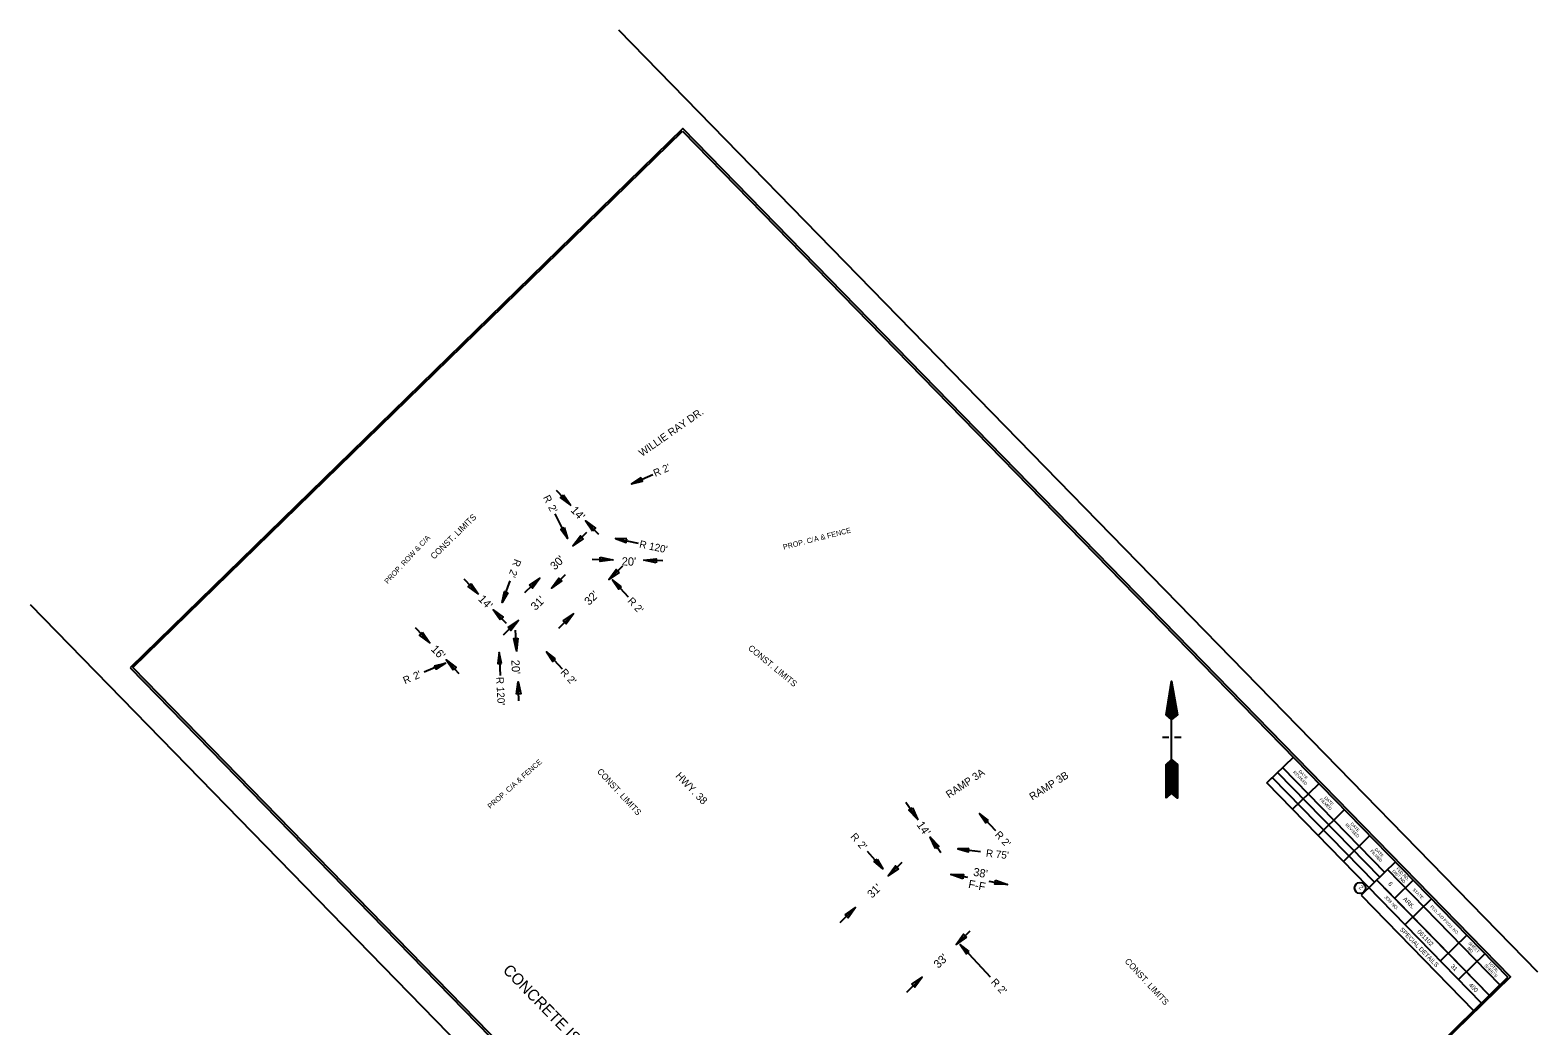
# Model space of a CAD drawing. Extents: x 1309825 to 1312816, y 238906 to 242017.
# Drawn here: x 1309825 to 1310833, y 241351 to 242017 of the extents above; entities that cross this region are included whole.
import ezdxf

# ---------------------------------------------------------------- set-up
doc = ezdxf.new("R2010")
doc.units = 0
for name, color, linetype in [('R_Annotation', 7, 'Continuous'), ('R_Border', 7, 'Continuous'), ('R_Dimension', 7, 'Continuous'), ('R_No Plot', 7, 'Continuous'), ('R_North Arrow', 7, 'Continuous')]:
    doc.layers.add(name, color=color, linetype=linetype)

msp = doc.modelspace()

# ---------------------------------------------------------------- linework, layer by layer
at = {"layer": 'R_Border'}
for p, q in [((1310832.9, 241386.9), (1310218.4, 242016.8)), ((1309893.3, 241590.7), (1310261, 241949.3)), ((1310261, 241949.3), (1310812.9, 241383.5)), ((1309824.7, 241632.8), (1310439.2, 241002.8)), ((1310445.2, 241024.8), (1309893.3, 241590.7)), ((1310651.6, 241513.5), (1310669.4, 241530.7)), ((1310651.6, 241513.5), (1310655.3, 241517.1)), ((1310655.3, 241517.1), (1310723.7, 241447)), ((1310658.8, 241520.5), (1310727.1, 241450.4)), ((1310662.1, 241523.7), (1310730.5, 241453.6)), ((1310795.2, 241366.2), (1310651.6, 241513.5)), ((1310668.8, 241495.8), (1310686.2, 241512.7)), ((1310685.9, 241478.3), (1310703.2, 241495.3)), ((1310702.8, 241461), (1310720.1, 241477.9)), ((1310737.6, 241460.7), (1310714.8, 241438.3)), ((1310807.6, 241378.3), (1310732.4, 241455.5)), ((1310800.5, 241371.4), (1310725.3, 241448.5)), ((1310749.6, 241448.4), (1310737.2, 241436.3)), ((1310714.8, 241438.3), (1310790, 241361.1)), ((1310730.4, 241443.2), (1310800.5, 241371.4)), ((1310761.7, 241436), (1310744.1, 241418.7)), ((1310785.4, 241411.7), (1310767.8, 241394.5)), ((1310797.6, 241399.3), (1310779.9, 241382)), ((1310445.2, 241024.8), (1310812.9, 241383.5)), ((1310807.7, 241378.4), (1310807.7, 241378.4))]:
    msp.add_line(p, q, dxfattribs=at)
msp.add_circle((1310714, 241443.2), 3.67, dxfattribs=at)
at = {"layer": 'R_Dimension'}
for p, q in [((1310226.8, 241713.5), (1310241, 241719.7)), ((1310176.5, 241709.3), (1310186.3, 241699)), ((1310184.1, 241677), (1310175.7, 241693.4)), ((1310204.9, 241679.5), (1310196.1, 241688.7)), ((1310196.8, 241680.9), (1310187.6, 241672)), ((1310216.2, 241676.9), (1310231.3, 241673.7)), ((1310200.4, 241663), (1310214.7, 241662.7)), ((1310220.7, 241658.3), (1310211.6, 241649.5)), ((1310247.7, 241662), (1310235, 241662.3)), ((1310114.7, 241649.9), (1310124.5, 241639.6)), ((1310140.4, 241634.1), (1310145.7, 241648.5)), ((1310155.5, 241640.8), (1310165.8, 241650.7)), ((1310182.5, 241652.6), (1310173.4, 241643.7)), ((1310214.1, 241649.2), (1310224.6, 241637.9)), ((1310143.1, 241620.1), (1310134.3, 241629.3)), ((1310178.2, 241617), (1310188.4, 241626.9)), ((1310082.2, 241617.3), (1310092.1, 241607)), ((1310141.3, 241612.5), (1310151.5, 241622.4)), ((1310149.1, 241615.7), (1310149.8, 241601.4)), ((1310138.2, 241600.7), (1310138.9, 241585.3)), ((1310169.9, 241601), (1310180.4, 241589.7)), ((1310102.4, 241593.5), (1310088.2, 241587.5)), ((1310111.6, 241586.5), (1310102.9, 241595.7)), ((1310151.5, 241568.4), (1310150.9, 241581.1)), ((1310410.3, 241500.6), (1310418.4, 241488.8)), ((1310459.6, 241493), (1310470.1, 241481.7)), ((1310433.7, 241466.7), (1310426.5, 241477.2)), ((1310394.9, 241456.1), (1310384.7, 241467.7)), ((1310444.9, 241469.4), (1310460.2, 241467.6)), ((1310407.5, 241460.2), (1310398.4, 241451.3)), ((1310451.8, 241450.2), (1310440.4, 241452.1)), ((1310465.7, 241447.8), (1310478.2, 241445.6)), ((1310366.3, 241420.1), (1310376.5, 241430.1)), ((1310453, 241414.4), (1310443.8, 241405.5)), ((1310446.5, 241405.5), (1310466.6, 241383.8)), ((1310410.9, 241373.6), (1310421.2, 241383.5))]:
    msp.add_line(p, q, dxfattribs=at)
for points in [[(1310233.1, 241717.6), (1310226.8, 241713.5), (1310234.1, 241715.3)], [(1310181.3, 241706.2), (1310186, 241699.3), (1310179.3, 241704.3)], [(1310200.8, 241681.8), (1310196.1, 241688.7), (1310202.8, 241683.7)], [(1310181.8, 241684.2), (1310184.1, 241677), (1310179.6, 241683)], [(1310194.5, 241676.7), (1310187.6, 241672), (1310192.6, 241678.7)], [(1310223.7, 241676.6), (1310216.2, 241676.9), (1310223.2, 241674.2)], [(1310205.9, 241664.3), (1310214.1, 241662.7), (1310205.9, 241661.5)], [(1310243.2, 241660.7), (1310235, 241662.3), (1310243.2, 241663.4)], [(1310119.5, 241646.8), (1310124.2, 241639.9), (1310117.5, 241644.9)], [(1310158.6, 241645.6), (1310165.4, 241650.4), (1310160.5, 241643.6)], [(1310180.2, 241648.5), (1310173.4, 241643.7), (1310178.3, 241650.4)], [(1310218.5, 241654.2), (1310211.6, 241649.5), (1310216.6, 241656.2)], [(1310220.1, 241644.6), (1310214.1, 241649.2), (1310218.3, 241643)], [(1310144.1, 241640.6), (1310140.4, 241634.1), (1310141.8, 241641.5)], [(1310139, 241622.4), (1310134.3, 241629.3), (1310141, 241624.3)], [(1310181.2, 241621.8), (1310188.1, 241626.6), (1310183.1, 241619.8)], [(1310144.3, 241617.3), (1310151.2, 241622.1), (1310146.2, 241615.4)], [(1310087.1, 241614.2), (1310091.8, 241607.3), (1310085.1, 241612.3)], [(1310150.7, 241610.2), (1310149.8, 241601.9), (1310148, 241610.1)], [(1310139.8, 241593.4), (1310138.2, 241600.7), (1310137.3, 241593.2)], [(1310175.9, 241596.4), (1310169.9, 241601), (1310174.1, 241594.7)], [(1310095.1, 241591.8), (1310102.4, 241593.5), (1310096.1, 241589.5)], [(1310107.6, 241588.8), (1310102.9, 241595.7), (1310109.5, 241590.7)], [(1310149.9, 241572.8), (1310150.9, 241581.1), (1310152.7, 241573)], [(1310414.6, 241496.8), (1310418.1, 241489.2), (1310412.3, 241495.2)], [(1310465.6, 241488.4), (1310459.6, 241493), (1310463.8, 241486.7)], [(1310430, 241469.6), (1310426.5, 241477.2), (1310432.3, 241471.2)], [(1310452.4, 241469.7), (1310444.9, 241469.4), (1310452.1, 241467.3)], [(1310391, 241462.5), (1310394.9, 241456.1), (1310389.1, 241460.8)], [(1310405.3, 241456.1), (1310398.4, 241451.3), (1310403.3, 241458)], [(1310448.3, 241449.4), (1310440.4, 241452.1), (1310448.8, 241452.1)], [(1310470.3, 241448.4), (1310478.2, 241445.6), (1310469.8, 241445.7)], [(1310369.7, 241425.3), (1310376.5, 241430.1), (1310371.6, 241423.3)], [(1310450.7, 241410.3), (1310443.8, 241405.5), (1310448.8, 241412.3)], [(1310452.5, 241400.8), (1310446.5, 241405.5), (1310450.7, 241399.2)], [(1310414.3, 241378.8), (1310421.2, 241383.5), (1310416.2, 241376.8)]]:
    msp.add_lwpolyline(points, close=True, dxfattribs=at)
at = {"layer": 'R_No Plot'}
msp.add_lwpolyline([(1309891.6, 241590.5), (1310445, 241023.2), (1310814.6, 241383.7), (1310261.2, 241951)], close=True, dxfattribs=at)
at = {"layer": 'R_North Arrow'}
for p, q in [((1310589.3, 241573.8), (1310587.1, 241576)), ((1310589.2, 241574.6), (1310587.2, 241576.6)), ((1310589.2, 241574.2), (1310587.2, 241576.3)), ((1310589, 241575.5), (1310587.3, 241577.2)), ((1310589.1, 241575.1), (1310587.3, 241576.9)), ((1310588.9, 241576.3), (1310587.4, 241577.8)), ((1310589, 241575.9), (1310587.4, 241577.5)), ((1310588.7, 241577.2), (1310587.5, 241578.4)), ((1310588.8, 241576.8), (1310587.5, 241578.1)), ((1310588.6, 241578), (1310587.6, 241579)), ((1310588.7, 241577.6), (1310587.6, 241578.7)), ((1310588.5, 241578.9), (1310587.7, 241579.6)), ((1310588.5, 241578.5), (1310587.7, 241579.3)), ((1310588.3, 241579.7), (1310587.8, 241580.2)), ((1310588.4, 241579.3), (1310587.8, 241579.9)), ((1310588.2, 241580.6), (1310587.9, 241580.8)), ((1310588.2, 241580.2), (1310587.9, 241580.5)), ((1310588, 241581.4), (1310588, 241581.4)), ((1310588.1, 241581), (1310588, 241581.1)), ((1310591.6, 241560.2), (1310585.5, 241566.3)), ((1310591.6, 241559.8), (1310585.5, 241566)), ((1310591.4, 241561.1), (1310585.6, 241566.9)), ((1310591.5, 241560.6), (1310585.6, 241566.6)), ((1310591.3, 241561.9), (1310585.7, 241567.5)), ((1310591.4, 241561.5), (1310585.7, 241567.2)), ((1310591.1, 241562.8), (1310585.8, 241568.1)), ((1310591.2, 241562.3), (1310585.8, 241567.8)), ((1310591, 241563.6), (1310585.9, 241568.7)), ((1310591.1, 241563.2), (1310585.9, 241568.4)), ((1310590.9, 241564.5), (1310586, 241569.3)), ((1310590.9, 241564), (1310586, 241569)), ((1310590.7, 241565.3), (1310586.1, 241569.9)), ((1310590.8, 241564.9), (1310586.1, 241569.6)), ((1310590.6, 241566.2), (1310586.2, 241570.5)), ((1310590.7, 241565.7), (1310586.2, 241570.2)), ((1310590.4, 241567), (1310586.3, 241571.1)), ((1310590.5, 241566.6), (1310586.3, 241570.8)), ((1310590.3, 241567.9), (1310586.4, 241571.7)), ((1310590.4, 241567.4), (1310586.4, 241571.4)), ((1310590.2, 241568.7), (1310586.5, 241572.4)), ((1310590.2, 241568.3), (1310586.5, 241572)), ((1310590, 241569.6), (1310586.6, 241573)), ((1310590.1, 241569.1), (1310586.6, 241572.7)), ((1310589.9, 241570.4), (1310586.7, 241573.6)), ((1310589.9, 241570), (1310586.7, 241573.3)), ((1310589.7, 241571.3), (1310586.8, 241574.2)), ((1310589.8, 241570.8), (1310586.8, 241573.9)), ((1310589.6, 241572.1), (1310586.9, 241574.8)), ((1310589.7, 241571.7), (1310586.9, 241574.5)), ((1310589.4, 241573), (1310587, 241575.4)), ((1310589.5, 241572.5), (1310587, 241575.1)), ((1310589.4, 241573.4), (1310587.1, 241575.7)), ((1310586.8, 241556.8), (1310584.3, 241559.3)), ((1310584.7, 241558.6), (1310584.3, 241559)), ((1310588.3, 241556.1), (1310584.4, 241559.9)), ((1310588.1, 241555.9), (1310584.4, 241559.6)), ((1310588.7, 241556.4), (1310584.5, 241560.5)), ((1310588.5, 241556.2), (1310584.5, 241560.2)), ((1310589.1, 241556.7), (1310584.6, 241561.1)), ((1310588.9, 241556.5), (1310584.6, 241560.8)), ((1310589.5, 241557), (1310584.7, 241561.7)), ((1310589.3, 241556.9), (1310584.7, 241561.4)), ((1310589.9, 241557.3), (1310584.8, 241562.4)), ((1310589.7, 241557.2), (1310584.8, 241562)), ((1310590.2, 241557.7), (1310584.9, 241563)), ((1310590, 241557.5), (1310584.9, 241562.7)), ((1310590.4, 241557.8), (1310585, 241563.3)), ((1310590.8, 241558.2), (1310585.1, 241563.9)), ((1310590.6, 241558), (1310585.1, 241563.6)), ((1310591.2, 241558.5), (1310585.2, 241564.5)), ((1310591, 241558.3), (1310585.2, 241564.2)), ((1310591.6, 241558.8), (1310585.3, 241565.1)), ((1310591.4, 241558.6), (1310585.3, 241564.8)), ((1310591.7, 241559.4), (1310585.4, 241565.7)), ((1310591.8, 241559), (1310585.4, 241565.4)), ((1310588, 241529), (1310588, 241555.8)), ((1310581.9, 241544), (1310586.2, 241544)), ((1310589.9, 241544), (1310594.4, 241544)), ((1310591.8, 241518.4), (1310584.3, 241525.9)), ((1310591.8, 241518.1), (1310584.3, 241525.6)), ((1310591.8, 241518.8), (1310584.5, 241526)), ((1310591.8, 241519.1), (1310584.7, 241526.2)), ((1310591.8, 241519.5), (1310584.9, 241526.4)), ((1310591.8, 241519.9), (1310585.1, 241526.5)), ((1310591.8, 241520.2), (1310585.3, 241526.7)), ((1310591.8, 241520.6), (1310585.5, 241526.8)), ((1310591.8, 241520.9), (1310585.7, 241527)), ((1310591.8, 241521.3), (1310585.9, 241527.2)), ((1310591.8, 241521.6), (1310586.1, 241527.3)), ((1310591.8, 241522), (1310586.3, 241527.5)), ((1310591.8, 241522.3), (1310586.5, 241527.7)), ((1310591.8, 241522.7), (1310586.7, 241527.8)), ((1310591.8, 241523), (1310586.8, 241528)), ((1310591.8, 241523.4), (1310587, 241528.1)), ((1310591.8, 241523.7), (1310587.2, 241528.3)), ((1310591.8, 241524.1), (1310587.4, 241528.5)), ((1310591.8, 241524.5), (1310587.6, 241528.6)), ((1310591.8, 241524.8), (1310587.8, 241528.8)), ((1310591.8, 241525.2), (1310588, 241528.9)), ((1310591.8, 241525.5), (1310589.9, 241527.4)), ((1310591.8, 241517.7), (1310584.3, 241525.2)), ((1310591.8, 241517.4), (1310584.3, 241524.9)), ((1310591.8, 241517), (1310584.3, 241524.5)), ((1310591.8, 241516.7), (1310584.3, 241524.2)), ((1310591.8, 241516.3), (1310584.3, 241523.8)), ((1310591.8, 241516), (1310584.3, 241523.5)), ((1310591.8, 241515.6), (1310584.3, 241523.1)), ((1310591.8, 241515.3), (1310584.3, 241522.8)), ((1310591.8, 241514.9), (1310584.3, 241522.4)), ((1310591.8, 241514.6), (1310584.3, 241522.1)), ((1310591.8, 241514.2), (1310584.3, 241521.7)), ((1310591.8, 241513.8), (1310584.3, 241521.3)), ((1310591.8, 241513.5), (1310584.3, 241521)), ((1310591.8, 241513.1), (1310584.3, 241520.6)), ((1310591.8, 241512.8), (1310584.3, 241520.3)), ((1310591.8, 241512.4), (1310584.3, 241519.9)), ((1310591.8, 241512.1), (1310584.3, 241519.6)), ((1310591.8, 241511.7), (1310584.3, 241519.2)), ((1310591.8, 241511.4), (1310584.3, 241518.9)), ((1310591.8, 241511), (1310584.3, 241518.5)), ((1310591.8, 241510.7), (1310584.3, 241518.2)), ((1310591.8, 241510.3), (1310584.3, 241517.8)), ((1310591.8, 241510), (1310584.3, 241517.5)), ((1310591.8, 241509.6), (1310584.3, 241517.1)), ((1310591.8, 241509.3), (1310584.3, 241516.8)), ((1310591.8, 241508.9), (1310584.3, 241516.4)), ((1310591.8, 241508.5), (1310584.3, 241516)), ((1310591.8, 241508.2), (1310584.3, 241515.7)), ((1310591.8, 241507.8), (1310584.3, 241515.3)), ((1310591.8, 241507.5), (1310584.3, 241515)), ((1310591.8, 241507.1), (1310584.3, 241514.6)), ((1310591.8, 241506.8), (1310584.3, 241514.3)), ((1310591.8, 241506.4), (1310584.3, 241513.9)), ((1310591.8, 241506.1), (1310584.3, 241513.6)), ((1310591.8, 241505.7), (1310584.3, 241513.2)), ((1310591.8, 241505.4), (1310584.3, 241512.9)), ((1310591.8, 241505), (1310584.3, 241512.5)), ((1310591.8, 241504.7), (1310584.3, 241512.2)), ((1310591.8, 241504.3), (1310584.3, 241511.8)), ((1310591.8, 241503.9), (1310584.3, 241511.4)), ((1310591.8, 241503.6), (1310584.3, 241511.1)), ((1310591.2, 241503.8), (1310584.3, 241510.7)), ((1310589.1, 241505.6), (1310584.3, 241510.4)), ((1310587.9, 241506.4), (1310584.3, 241510)), ((1310587.7, 241506.2), (1310584.3, 241509.7)), ((1310587.6, 241506.1), (1310584.3, 241509.3)), ((1310587.4, 241505.9), (1310584.3, 241509)), ((1310587.2, 241505.7), (1310584.3, 241508.6)), ((1310587, 241505.6), (1310584.3, 241508.3)), ((1310586.8, 241505.4), (1310584.3, 241507.9)), ((1310586.6, 241505.3), (1310584.3, 241507.6)), ((1310586.4, 241505.1), (1310584.3, 241507.2)), ((1310586.2, 241504.9), (1310584.3, 241506.9)), ((1310586, 241504.8), (1310584.3, 241506.5)), ((1310585.8, 241504.6), (1310584.3, 241506.1)), ((1310585.6, 241504.4), (1310584.3, 241505.8)), ((1310585.4, 241504.3), (1310584.3, 241505.4)), ((1310585.2, 241504.1), (1310584.3, 241505.1)), ((1310585, 241504), (1310584.3, 241504.7)), ((1310584.9, 241503.8), (1310584.3, 241504.4)), ((1310584.7, 241503.6), (1310584.3, 241504)), ((1310584.5, 241503.5), (1310584.3, 241503.7))]:
    msp.add_line(p, q, dxfattribs=at)
for points in [[(1310588, 241555.8), (1310584.3, 241559), (1310588, 241581.5), (1310591.8, 241559)], [(1310584.3, 241503.3), (1310584.3, 241525.8), (1310588, 241529), (1310591.8, 241525.8), (1310591.8, 241503.3), (1310588, 241506.5)]]:
    msp.add_lwpolyline(points, close=True, dxfattribs=at)

# ---------------------------------------------------------------- texts
at = {"layer": 'R_Annotation'}
for s, height, rotation, p in [('WILLIE RAY DR.', 5, 34.9116, (1310233.8, 241731.4)), ('CONST. LIMITS', 4.123, 44.3347, (1310094.8, 241662.7)), ('PROP. ROW & C/A', 3.5, 47.0318, (1310063.7, 241646.3)), ('PROP. C/A & FENCE', 3.5, 14.2913, (1310328.6, 241669.4)), ('CONST. LIMITS', 4.123, 320.5433, (1310304.4, 241602.9)), ('PROP. C/A & FENCE', 3.5, 41.7724, (1310132.4, 241495.9)), ('CONST. LIMITS', 4.123, 312.7047, (1310203.5, 241520.8)), ('HWY. 38', 5, 313.9593, (1310255.9, 241517.8)), ('RAMP 3A', 5, 33.7229, (1310439.1, 241503)), ('RAMP 3B', 5, 32.2345, (1310494.8, 241501.6)), ('CONST. LIMITS', 4.123, 312.7047, (1310556.3, 241393.9)), ('CONCRETE ISLAND DETAILS', 7.527, 314.2865, (1310140.3, 241387.7))]:
    msp.add_text(s, height=height, rotation=rotation, dxfattribs=at).set_placement(p)
at = {"layer": 'R_Border'}
for s, height, rotation, p in [('REVISED', 2, 314.2882, (1310669, 241520.4)), ('DATE', 2, 314.2882, (1310672.7, 241520.9)), ('FILMED', 2, 314.2882, (1310686.8, 241502.2)), ('DATE', 2, 314.2882, (1310689.9, 241503.3)), ('REVISED', 2, 314.2882, (1310703.8, 241485.3)), ('DATE', 2, 314.2882, (1310707.4, 241485.9)), ('FILMED', 2, 314.2882, (1310720.6, 241467.6)), ('DATE', 2, 314.2882, (1310723.5, 241468.8)), ('DIST.NO.', 2, 314.2882, (1310735.3, 241454.2)), ('FED.RD.', 2, 314.2882, (1310737.9, 241455.8)), ('2', 2.93, 314.2882, (1310712.9, 241443.3)), ('6', 2.93, 314.2882, (1310732.5, 241445.7)), ('JOB NO.', 2.2, 314.2882, (1310729.9, 241436.9)), ('ARK.', 2.93, 314.2882, (1310742.4, 241435.5)), ('STATE', 2, 314.2882, (1310748.9, 241441.9)), ('FED. AID PROJ. NO.', 2, 314.2882, (1310760.7, 241430.4)), ('SPECIAL DETAILS', 2.925, 314.2883, (1310740.3, 241415.1)), ('061102', 2.92, 314.2883, (1310751.9, 241413.7)), ('SHEET', 2, 314.2882, (1310786.2, 241406.1)), ('NO.', 2, 314.2882, (1310785.5, 241402.6)), ('31', 2.93, 314.2883, (1310774.3, 241390.5)), ('SHEETS', 2, 314.2882, (1310796.9, 241391.1)), ('TOTAL', 2, 314.2882, (1310799.4, 241392.7)), ('400', 2.95, 314.2883, (1310786.4, 241378))]:
    msp.add_text(s, height=height, rotation=rotation, dxfattribs=at).set_placement(p)
at = {"layer": 'R_Dimension'}
for s, height, rotation, p in [("R 2'", 4.95, 23.7245, (1310242.7, 241718)), ('R', 4.95, 297.0039, (1310167.5, 241704.4)), ("2'", 4.95, 297.0039, (1310170.9, 241697.8)), ("14'", 5.5, 313.7081, (1310185.7, 241695.4)), ("R 120'", 4.95, 348.1795, (1310231.7, 241670.9)), ('R', 4.95, 249.7928, (1310148.6, 241663.6)), ("30'", 5.5, 44.2006, (1310175.6, 241655.4)), ("20'", 5.5, 358.6844, (1310220.2, 241658.9)), ("2'", 4.95, 249.7928, (1310146.1, 241656.6)), ("14'", 5.5, 313.7081, (1310123.9, 241636)), ("31'", 5.5, 44.2006, (1310162.6, 241628.4)), ("32'", 5.5, 44.2006, (1310198.4, 241631.8)), ("R 2'", 4.95, 312.7498, (1310223.8, 241634.8)), ("16'", 5.5, 313.7081, (1310092.3, 241602.5)), ("2'", 4.95, 22.9249, (1310082.1, 241582.3)), ("20'", 5.5, 272.9831, (1310146.4, 241595.6)), ("R 2'", 4.95, 312.7498, (1310178.9, 241587.1)), ('R', 4.95, 22.9249, (1310075.3, 241579.4)), ("R 120'", 4.95, 272.9155, (1310136.3, 241584.2)), ("14'", 5.5, 304.6895, (1310417.2, 241485.4)), ('R', 4.95, 311.5024, (1310372.9, 241477.3)), ("R 2'", 4.95, 312.7498, (1310469.4, 241478.5)), ("2'", 4.95, 311.5024, (1310377.8, 241471.8)), ("R 75'", 4.95, 353.4813, (1310463.6, 241464.2)), ("38'", 5.5, 350.2147, (1310455, 241451.4)), ("31'", 5.5, 44.2006, (1310387.6, 241436)), ('F-F', 5.5, 349.3708, (1310451.7, 241443.3)), ("33'", 5.5, 44.2006, (1310432, 241389.1)), ("R 2'", 4.95, 312.7498, (1310466.8, 241379.9))]:
    msp.add_text(s, height=height, rotation=rotation, dxfattribs=at).set_placement(p)

doc.saveas('drawing.dxf')
